(* Logix 5000 project; controller EFlo_iQ_Controller vendor 1 type 14 code 74 rev 20.12; software revision 20.01 *)

TASK MainTask (continuous, watchdog 500 ms) : MainProgram

MODULES
   Local : vendor 1 type 14 code 74 (1768Ctrl5Slot 0, Compact 0, rev 20.12)
      ENET : 1768-ENBT (1768 1, Ethernet 10.10.20.11, rev 3.1)
         EFlo_iQ : ETHERNET-MODULE (Ethernet 192.168.2.16, rev 1.1, Output RPI 10 ms)   // Graco E-Flo iQ Advanced Map
END_MODULES

TYPE ActivePump :
STRUCT
   ControlBits : EFlo_iQ_Control_Bits;
   StatusBits : EFlo_iQ_Status_Bits;
   Information : EFlo_iQ_Pump_Information;
   AdditionalInformation : EFlo_iQ_Pump_Information_ActivePumpOnly;
   DispenseInformation : EFlo_iQ_Dispense_Information;
   StyleInformation : E_Flo_iQ_Style;
   HeartbeatLogic : EFlo_iQ_HeartbeatLogic;
   DataExchange : EFlo_iQ_Pump_Data_Exchange;
END_STRUCT
END_TYPE

TYPE E_Flo_iQ_Style :
STRUCT
   DesiredActiveStyleNumber : INT;
   StyleFieldbusPrechargeRequested : INT;   // XXXX.X bars
   StyleFieldbusFlowrateRequested : INT;   // XXXX cc/min
   StyleFieldbusShotSizeRequested : INT;   // XXXX.XX cc
   StyleFieldbusDValveOnDelayRequested : INT;   // XXXX ms
   StyleFieldbusDValveOffDelayRequested : INT;   // XXXX ms
   StyleFieldbusMotorOnDelayRequested : INT;   // XXXX ms
   StyleFieldbusMotorOffDelayRequested : INT;   // XXXX ms
   ActiveStyleLoaded : INT;
   ActiveStylePrecharge : INT;   // XXXX.X bars
   ActiveStyleFlowrate : INT;   // XXXX cc/min
   ActiveStyleShotSize : INT;   // XXXX.XX cc
   ActiveStyleDispenseValveOnDelay : INT;   // XXXX ms
   ActiveStyleDispenseValveOffDelay : INT;   // XXXX ms
   ActiveStyleMotorOnDelay : INT;   // XXXX ms
   ActiveStyleMotorOffDelay : INT;   // XXXX ms
   ActualStyleFieldbusRequestPrecharge : INT;   // XXXX.X bars
   ActualStyleFieldbusRequestFlowrate : INT;   // XXXX cc/min
   ActualStyleFieldbusRequestShotSize : INT;   // XXXX.XX cc
   ActualStyleFieldbusRequestDValveOnDeley : INT;   // XXXX ms
   ActualStyleFieldbusRequestDValveOffDeley : INT;   // XXXX ms
   ActualStyleFieldbusRequestMotorOnDelay : INT;   // XXXX ms
   ActualStyleFieldbusRequestMotorOffDelay : INT;   // XXXX ms
END_STRUCT
END_TYPE

TYPE EFlo_iQ_Control_Bits :
STRUCT
   SystemEnableRequest : BOOL;
   SystemDisableRequest : BOOL;
   PLCLockoutRequest : BOOL;
   StyleEnableSignal : BOOL;
   StyleGoSignal : BOOL;
   StyleDispenseCompleted : BOOL;
   TandemCrossoverRequest : BOOL;
   PrimingRequest : BOOL;
   ValveDepressurizationRequest : BOOL;
   PlatenDepressurizationRequest : BOOL;
   AutoDepressurizationCancelRequest : BOOL;
   AcknowledgeClearErrorsRequest : BOOL;
END_STRUCT
END_TYPE

TYPE EFlo_iQ_Dispense_Information :
STRUCT
   ActualAmountDispense : DINT;   // XXXX.XX cc
   ActualShotSizeRequested : DINT;   // XXXX.XX cc
END_STRUCT
END_TYPE

TYPE EFlo_iQ_HeartbeatLogic :
STRUCT
   HeartbeatFailure : BOOL;
   EFlo_iQ_Disconnected : BOOL;
   Heartbeat_HighMonitor : COUNTER;
   Heartbeat_LowMonitor : COUNTER;
   Heartbeat_MonitorTimer : TIMER;
   Heartbeat_StopMonitorTimer : BOOL;
END_STRUCT
END_TYPE

TYPE EFlo_iQ_Pump_Data_Exchange :
STRUCT
   PumpDataExchangeActiveCommand : INT;
   PumpDataExchangeActiveValue : DINT;
END_STRUCT
END_TYPE

TYPE EFlo_iQ_Pump_Information :
STRUCT
   ActualPumpFlowrate : INT;   // XXXX cc/min
   OutletPumpPressure : INT;   // XXXX.X bars
END_STRUCT
END_TYPE

TYPE EFlo_iQ_Pump_Information_ActivePumpOnly :
STRUCT
   ValvePressure : INT;   // XXXX.X bars
   PumpPosition : INT;   // X.XXXX inches
   PrimeFlowrateTarget : INT;   // XXXX cc/min
   PrimePressureTarget : INT;   // XXXX.X bars
END_STRUCT
END_TYPE

TYPE EFlo_iQ_Status_Bits :
STRUCT
   Heartbeat : BOOL;
   AutomationReady : BOOL;
   PLCControlActive : BOOL;
   SystemActive : BOOL;
   NoAlarmsPresent : BOOL;
   NoDeviationsPresent : BOOL;
   NoAdvisoriesPresent : BOOL;
   SystemReadyToDispense : BOOL;
   PrechargeDechargeActive : BOOL;
   DispenseInProcess : BOOL;
   DrumIsLow : BOOL;
   DrumIsEmpty : BOOL;
   PumpNotPrimed : BOOL;
   PumpInJobCycle : BOOL;
   PrimingActive : BOOL;
   ValveDepressurizationActive : BOOL;
   PlatenDepressurizationActive : BOOL;
   AutoDepressurizationActive : BOOL;
   AutoDepressurizationHappened : BOOL;
   PumpIsTryingToMove : BOOL;
   PumpIsActuallyMoving : BOOL;
   DispenseValveOpened : BOOL;
   PlatenValveOpened : BOOL;
   TandemActivePump : BOOL;   // 0 = Pump 1 1 = Pump 2
   iQModeActive : BOOL;
   ChangeoverHappenedDuringDispense : BOOL;
END_STRUCT
END_TYPE

TYPE EFlo_iQ_System_Data_Exchange :
STRUCT
   DesiredDataExchangeCommand : INT;
END_STRUCT
END_TYPE

TYPE InactivePump :
STRUCT
   StatusBits : EFlo_iQ_Status_Bits;
   Information : EFlo_iQ_Pump_Information;
   DataExchangeOutputs : EFlo_iQ_Pump_Data_Exchange;
   HeartbeatLogic : EFlo_iQ_HeartbeatLogic;
END_STRUCT
END_TYPE

VAR_GLOBAL   (* controller tags *)
   ActivePump : ActivePump; {access Read Only}
   InactivePump : InactivePump; {access Read Only}
   PumpsDesiredDataExchange : EFlo_iQ_System_Data_Exchange; {access Read Only}
END_VAR

PROGRAM MainProgram   (* main routine MainRoutine *)

ROUTINE EFlo_iQ_Data_Mapping   (* ladder *)
// Mapping_EFlo_iQ_Data_To_Tags
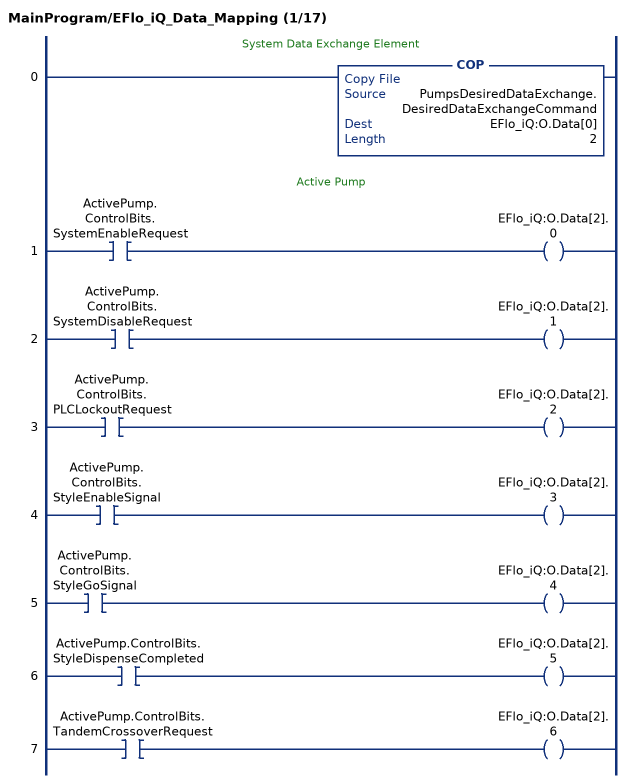
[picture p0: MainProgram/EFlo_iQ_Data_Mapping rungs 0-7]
   // System Data Exchange Element
   0: COP(PumpsDesiredDataExchange.DesiredDataExchangeCommand,EFlo_iQ:O.Data[0],2);
   // Active Pump
   1: XIC(ActivePump.ControlBits.SystemEnableRequest)OTE(EFlo_iQ:O.Data[2].0);
   2: XIC(ActivePump.ControlBits.SystemDisableRequest)OTE(EFlo_iQ:O.Data[2].1);
   3: XIC(ActivePump.ControlBits.PLCLockoutRequest)OTE(EFlo_iQ:O.Data[2].2);
   4: XIC(ActivePump.ControlBits.StyleEnableSignal)OTE(EFlo_iQ:O.Data[2].3);
   5: XIC(ActivePump.ControlBits.StyleGoSignal)OTE(EFlo_iQ:O.Data[2].4);
   6: XIC(ActivePump.ControlBits.StyleDispenseCompleted)OTE(EFlo_iQ:O.Data[2].5);
   7: XIC(ActivePump.ControlBits.TandemCrossoverRequest)OTE(EFlo_iQ:O.Data[2].6);
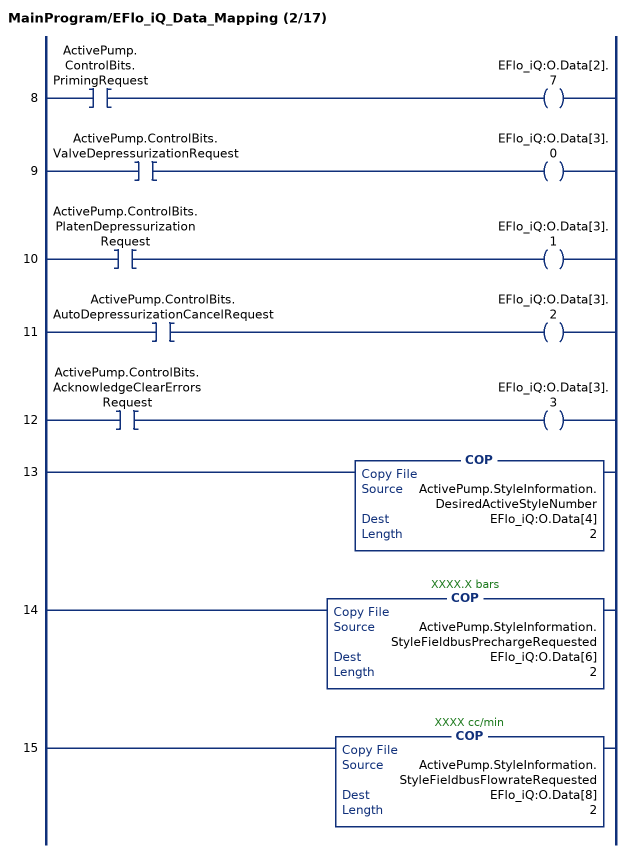
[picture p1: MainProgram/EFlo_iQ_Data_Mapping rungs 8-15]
   8: XIC(ActivePump.ControlBits.PrimingRequest)OTE(EFlo_iQ:O.Data[2].7);
   9: XIC(ActivePump.ControlBits.ValveDepressurizationRequest)OTE(EFlo_iQ:O.Data[3].0);
   10: XIC(ActivePump.ControlBits.PlatenDepressurizationRequest)OTE(EFlo_iQ:O.Data[3].1);
   11: XIC(ActivePump.ControlBits.AutoDepressurizationCancelRequest)OTE(EFlo_iQ:O.Data[3].2);
   12: XIC(ActivePump.ControlBits.AcknowledgeClearErrorsRequest)OTE(EFlo_iQ:O.Data[3].3);
   13: COP(ActivePump.StyleInformation.DesiredActiveStyleNumber,EFlo_iQ:O.Data[4],2);
   14: COP(ActivePump.StyleInformation.StyleFieldbusPrechargeRequested,EFlo_iQ:O.Data[6],2);
   15: COP(ActivePump.StyleInformation.StyleFieldbusFlowrateRequested,EFlo_iQ:O.Data[8],2);
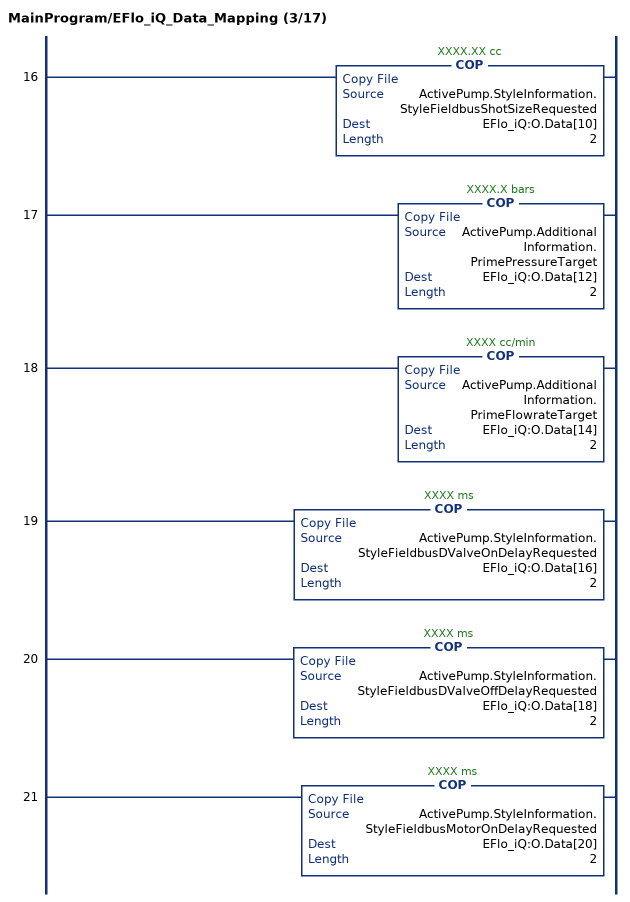
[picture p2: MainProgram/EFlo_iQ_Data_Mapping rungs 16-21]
   16: COP(ActivePump.StyleInformation.StyleFieldbusShotSizeRequested,EFlo_iQ:O.Data[10],2);
   17: COP(ActivePump.AdditionalInformation.PrimePressureTarget,EFlo_iQ:O.Data[12],2);
   18: COP(ActivePump.AdditionalInformation.PrimeFlowrateTarget,EFlo_iQ:O.Data[14],2);
   19: COP(ActivePump.StyleInformation.StyleFieldbusDValveOnDelayRequested,EFlo_iQ:O.Data[16],2);
   20: COP(ActivePump.StyleInformation.StyleFieldbusDValveOffDelayRequested,EFlo_iQ:O.Data[18],2);
   21: COP(ActivePump.StyleInformation.StyleFieldbusMotorOnDelayRequested,EFlo_iQ:O.Data[20],2);
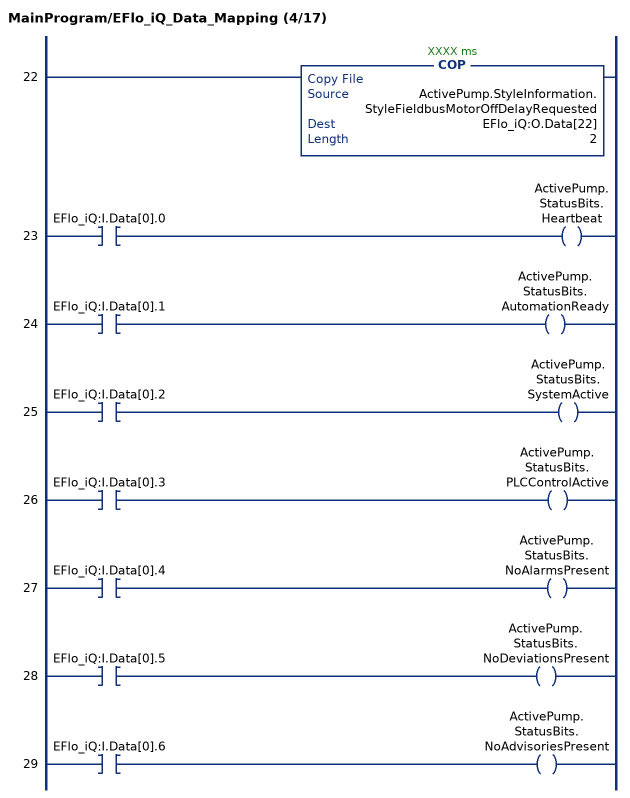
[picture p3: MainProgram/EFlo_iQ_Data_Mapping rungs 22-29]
   22: COP(ActivePump.StyleInformation.StyleFieldbusMotorOffDelayRequested,EFlo_iQ:O.Data[22],2);
   23: XIC(EFlo_iQ:I.Data[0].0)OTE(ActivePump.StatusBits.Heartbeat);
   24: XIC(EFlo_iQ:I.Data[0].1)OTE(ActivePump.StatusBits.AutomationReady);
   25: XIC(EFlo_iQ:I.Data[0].2)OTE(ActivePump.StatusBits.SystemActive);
   26: XIC(EFlo_iQ:I.Data[0].3)OTE(ActivePump.StatusBits.PLCControlActive);
   27: XIC(EFlo_iQ:I.Data[0].4)OTE(ActivePump.StatusBits.NoAlarmsPresent);
   28: XIC(EFlo_iQ:I.Data[0].5)OTE(ActivePump.StatusBits.NoDeviationsPresent);
   29: XIC(EFlo_iQ:I.Data[0].6)OTE(ActivePump.StatusBits.NoAdvisoriesPresent);
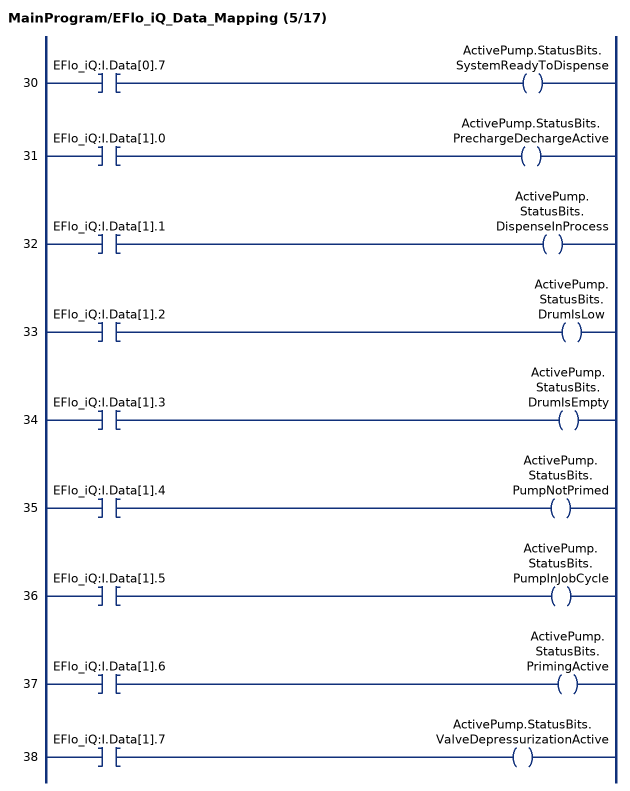
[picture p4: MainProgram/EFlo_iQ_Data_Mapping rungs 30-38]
   30: XIC(EFlo_iQ:I.Data[0].7)OTE(ActivePump.StatusBits.SystemReadyToDispense);
   31: XIC(EFlo_iQ:I.Data[1].0)OTE(ActivePump.StatusBits.PrechargeDechargeActive);
   32: XIC(EFlo_iQ:I.Data[1].1)OTE(ActivePump.StatusBits.DispenseInProcess);
   33: XIC(EFlo_iQ:I.Data[1].2)OTE(ActivePump.StatusBits.DrumIsLow);
   34: XIC(EFlo_iQ:I.Data[1].3)OTE(ActivePump.StatusBits.DrumIsEmpty);
   35: XIC(EFlo_iQ:I.Data[1].4)OTE(ActivePump.StatusBits.PumpNotPrimed);
   36: XIC(EFlo_iQ:I.Data[1].5)OTE(ActivePump.StatusBits.PumpInJobCycle);
   37: XIC(EFlo_iQ:I.Data[1].6)OTE(ActivePump.StatusBits.PrimingActive);
   38: XIC(EFlo_iQ:I.Data[1].7)OTE(ActivePump.StatusBits.ValveDepressurizationActive);
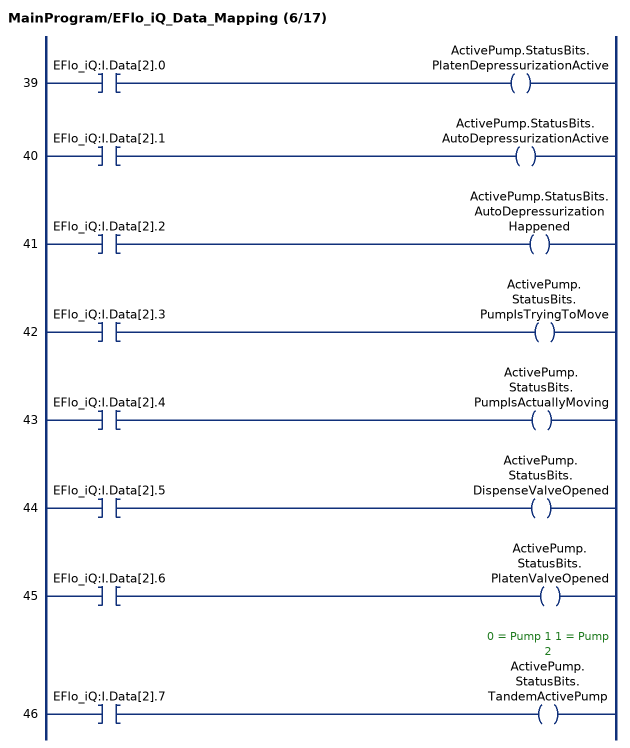
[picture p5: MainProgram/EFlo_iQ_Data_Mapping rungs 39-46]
   39: XIC(EFlo_iQ:I.Data[2].0)OTE(ActivePump.StatusBits.PlatenDepressurizationActive);
   40: XIC(EFlo_iQ:I.Data[2].1)OTE(ActivePump.StatusBits.AutoDepressurizationActive);
   41: XIC(EFlo_iQ:I.Data[2].2)OTE(ActivePump.StatusBits.AutoDepressurizationHappened);
   42: XIC(EFlo_iQ:I.Data[2].3)OTE(ActivePump.StatusBits.PumpIsTryingToMove);
   43: XIC(EFlo_iQ:I.Data[2].4)OTE(ActivePump.StatusBits.PumpIsActuallyMoving);
   44: XIC(EFlo_iQ:I.Data[2].5)OTE(ActivePump.StatusBits.DispenseValveOpened);
   45: XIC(EFlo_iQ:I.Data[2].6)OTE(ActivePump.StatusBits.PlatenValveOpened);
   46: XIC(EFlo_iQ:I.Data[2].7)OTE(ActivePump.StatusBits.TandemActivePump);
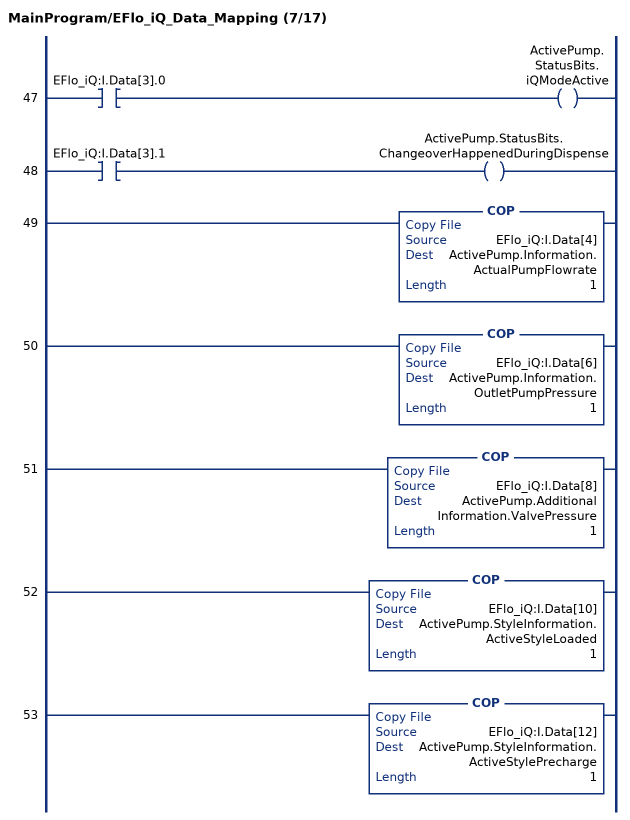
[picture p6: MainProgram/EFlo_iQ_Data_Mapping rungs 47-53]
   47: XIC(EFlo_iQ:I.Data[3].0)OTE(ActivePump.StatusBits.iQModeActive);
   48: XIC(EFlo_iQ:I.Data[3].1)OTE(ActivePump.StatusBits.ChangeoverHappenedDuringDispense);
   49: COP(EFlo_iQ:I.Data[4],ActivePump.Information.ActualPumpFlowrate,1);
   50: COP(EFlo_iQ:I.Data[6],ActivePump.Information.OutletPumpPressure,1);
   51: COP(EFlo_iQ:I.Data[8],ActivePump.AdditionalInformation.ValvePressure,1);
   52: COP(EFlo_iQ:I.Data[10],ActivePump.StyleInformation.ActiveStyleLoaded,1);
   53: COP(EFlo_iQ:I.Data[12],ActivePump.StyleInformation.ActiveStylePrecharge,1);
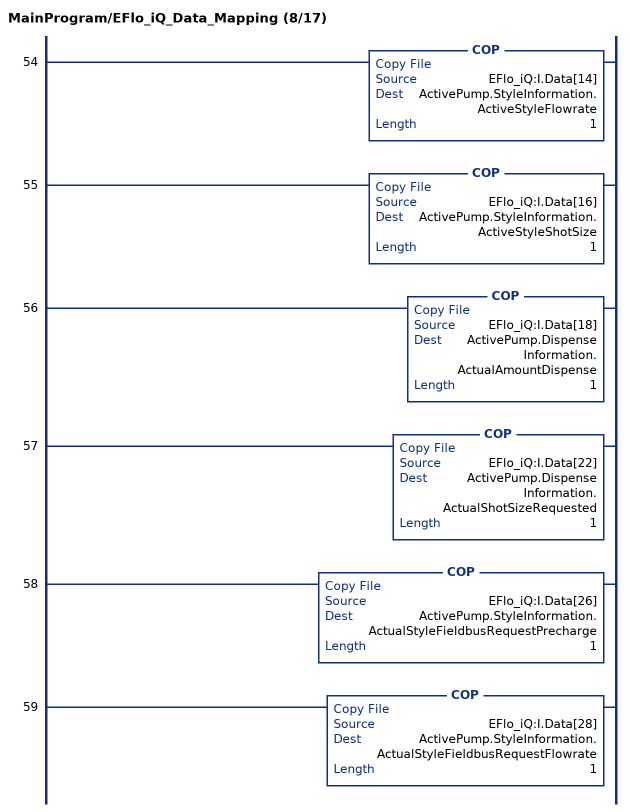
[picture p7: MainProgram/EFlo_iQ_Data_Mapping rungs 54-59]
   54: COP(EFlo_iQ:I.Data[14],ActivePump.StyleInformation.ActiveStyleFlowrate,1);
   55: COP(EFlo_iQ:I.Data[16],ActivePump.StyleInformation.ActiveStyleShotSize,1);
   56: COP(EFlo_iQ:I.Data[18],ActivePump.DispenseInformation.ActualAmountDispense,1);
   57: COP(EFlo_iQ:I.Data[22],ActivePump.DispenseInformation.ActualShotSizeRequested,1);
   58: COP(EFlo_iQ:I.Data[26],ActivePump.StyleInformation.ActualStyleFieldbusRequestPrecharge,1);
   59: COP(EFlo_iQ:I.Data[28],ActivePump.StyleInformation.ActualStyleFieldbusRequestFlowrate,1);
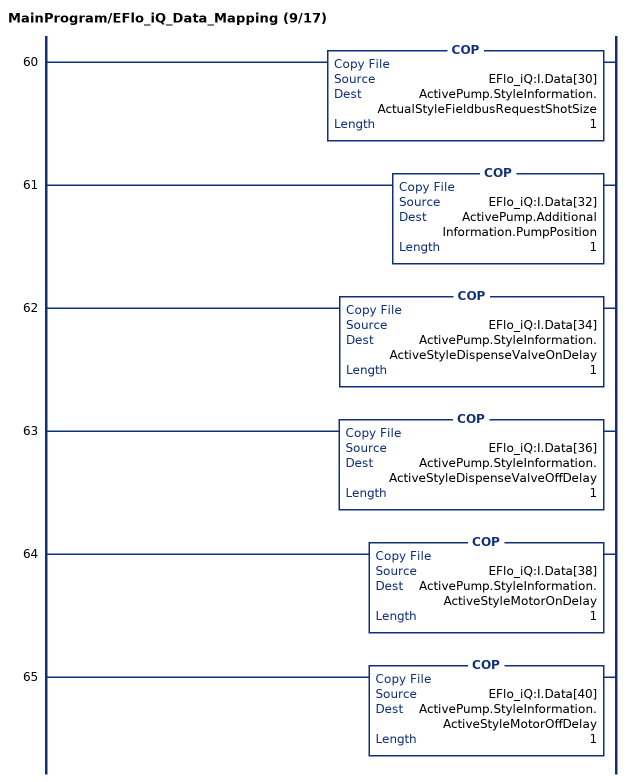
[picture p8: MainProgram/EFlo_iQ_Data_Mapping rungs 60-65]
   60: COP(EFlo_iQ:I.Data[30],ActivePump.StyleInformation.ActualStyleFieldbusRequestShotSize,1);
   61: COP(EFlo_iQ:I.Data[32],ActivePump.AdditionalInformation.PumpPosition,1);
   62: COP(EFlo_iQ:I.Data[34],ActivePump.StyleInformation.ActiveStyleDispenseValveOnDelay,1);
   63: COP(EFlo_iQ:I.Data[36],ActivePump.StyleInformation.ActiveStyleDispenseValveOffDelay,1);
   64: COP(EFlo_iQ:I.Data[38],ActivePump.StyleInformation.ActiveStyleMotorOnDelay,1);
   65: COP(EFlo_iQ:I.Data[40],ActivePump.StyleInformation.ActiveStyleMotorOffDelay,1);
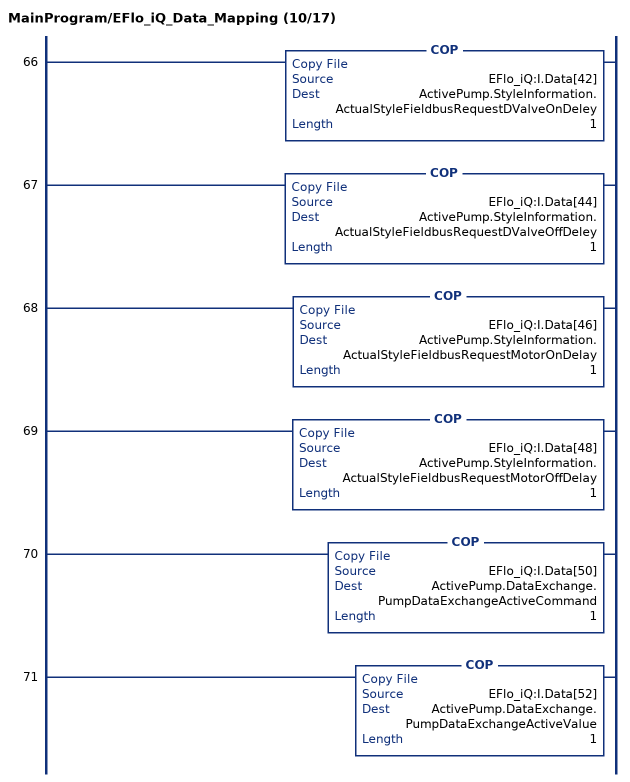
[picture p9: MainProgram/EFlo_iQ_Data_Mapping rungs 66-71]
   66: COP(EFlo_iQ:I.Data[42],ActivePump.StyleInformation.ActualStyleFieldbusRequestDValveOnDeley,1);
   67: COP(EFlo_iQ:I.Data[44],ActivePump.StyleInformation.ActualStyleFieldbusRequestDValveOffDeley,1);
   68: COP(EFlo_iQ:I.Data[46],ActivePump.StyleInformation.ActualStyleFieldbusRequestMotorOnDelay,1);
   69: COP(EFlo_iQ:I.Data[48],ActivePump.StyleInformation.ActualStyleFieldbusRequestMotorOffDelay,1);
   70: COP(EFlo_iQ:I.Data[50],ActivePump.DataExchange.PumpDataExchangeActiveCommand,1);
   71: COP(EFlo_iQ:I.Data[52],ActivePump.DataExchange.PumpDataExchangeActiveValue,1);
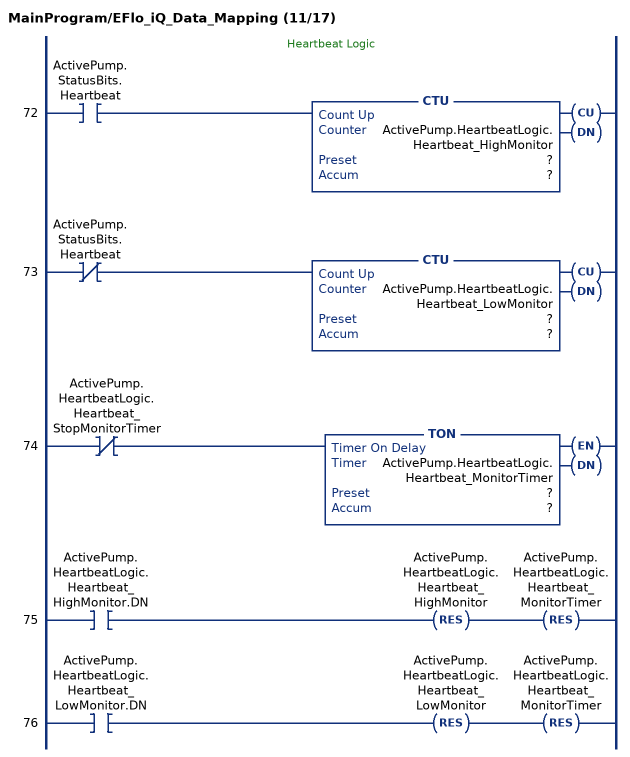
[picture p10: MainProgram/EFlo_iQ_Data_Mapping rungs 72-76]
   // Heartbeat Logic
   72: XIC(ActivePump.StatusBits.Heartbeat)CTU(ActivePump.HeartbeatLogic.Heartbeat_HighMonitor,?,?);
   73: XIO(ActivePump.StatusBits.Heartbeat)CTU(ActivePump.HeartbeatLogic.Heartbeat_LowMonitor,?,?);
   74: XIO(ActivePump.HeartbeatLogic.Heartbeat_StopMonitorTimer)TON(ActivePump.HeartbeatLogic.Heartbeat_MonitorTimer,?,?);
   75: XIC(ActivePump.HeartbeatLogic.Heartbeat_HighMonitor.DN)RES(ActivePump.HeartbeatLogic.Heartbeat_HighMonitor)RES(ActivePump.HeartbeatLogic.Heartbeat_MonitorTimer);
   76: XIC(ActivePump.HeartbeatLogic.Heartbeat_LowMonitor.DN)RES(ActivePump.HeartbeatLogic.Heartbeat_LowMonitor)RES(ActivePump.HeartbeatLogic.Heartbeat_MonitorTimer);
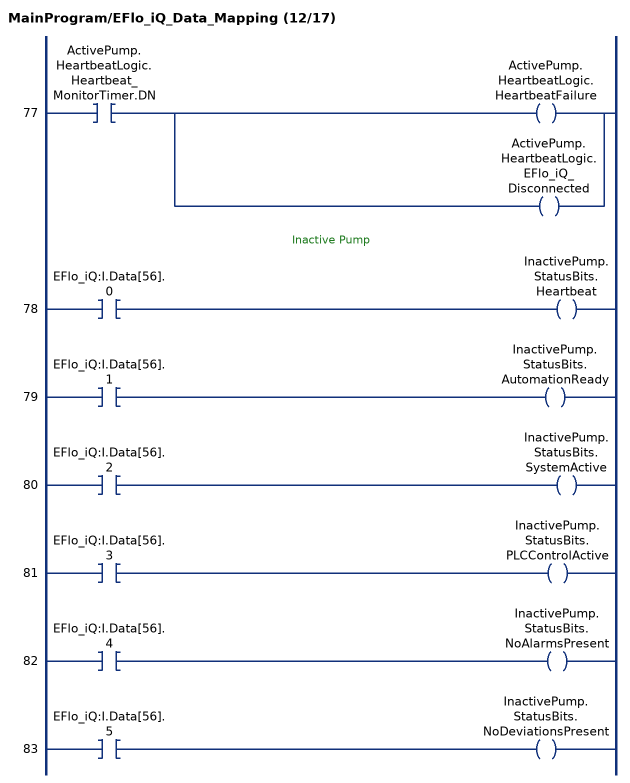
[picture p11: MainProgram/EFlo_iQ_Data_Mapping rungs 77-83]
   77: XIC(ActivePump.HeartbeatLogic.Heartbeat_MonitorTimer.DN)[OTE(ActivePump.HeartbeatLogic.HeartbeatFailure) ,OTE(ActivePump.HeartbeatLogic.EFlo_iQ_Disconnected) ];
   // Inactive Pump
   78: XIC(EFlo_iQ:I.Data[56].0)OTE(InactivePump.StatusBits.Heartbeat);
   79: XIC(EFlo_iQ:I.Data[56].1)OTE(InactivePump.StatusBits.AutomationReady);
   80: XIC(EFlo_iQ:I.Data[56].2)OTE(InactivePump.StatusBits.SystemActive);
   81: XIC(EFlo_iQ:I.Data[56].3)OTE(InactivePump.StatusBits.PLCControlActive);
   82: XIC(EFlo_iQ:I.Data[56].4)OTE(InactivePump.StatusBits.NoAlarmsPresent);
   83: XIC(EFlo_iQ:I.Data[56].5)OTE(InactivePump.StatusBits.NoDeviationsPresent);
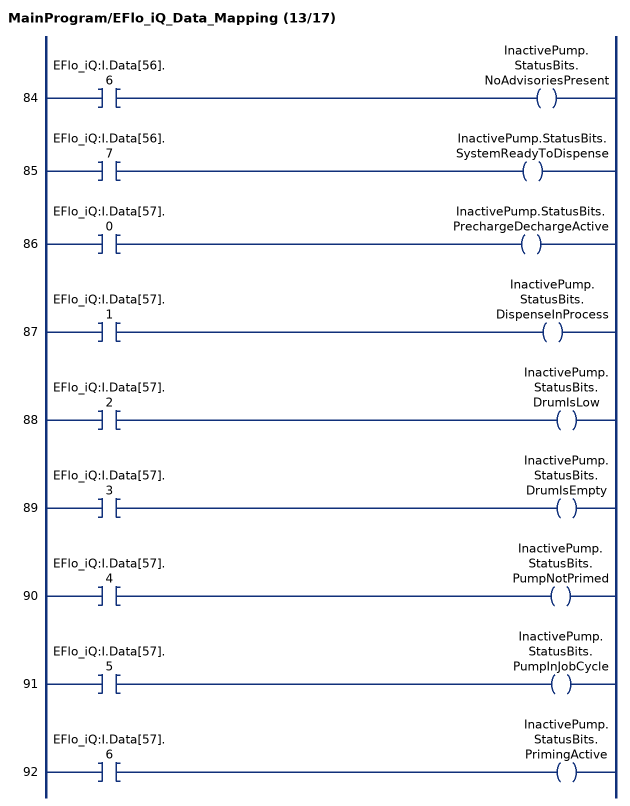
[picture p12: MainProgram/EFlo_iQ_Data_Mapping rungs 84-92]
   84: XIC(EFlo_iQ:I.Data[56].6)OTE(InactivePump.StatusBits.NoAdvisoriesPresent);
   85: XIC(EFlo_iQ:I.Data[56].7)OTE(InactivePump.StatusBits.SystemReadyToDispense);
   86: XIC(EFlo_iQ:I.Data[57].0)OTE(InactivePump.StatusBits.PrechargeDechargeActive);
   87: XIC(EFlo_iQ:I.Data[57].1)OTE(InactivePump.StatusBits.DispenseInProcess);
   88: XIC(EFlo_iQ:I.Data[57].2)OTE(InactivePump.StatusBits.DrumIsLow);
   89: XIC(EFlo_iQ:I.Data[57].3)OTE(InactivePump.StatusBits.DrumIsEmpty);
   90: XIC(EFlo_iQ:I.Data[57].4)OTE(InactivePump.StatusBits.PumpNotPrimed);
   91: XIC(EFlo_iQ:I.Data[57].5)OTE(InactivePump.StatusBits.PumpInJobCycle);
   92: XIC(EFlo_iQ:I.Data[57].6)OTE(InactivePump.StatusBits.PrimingActive);
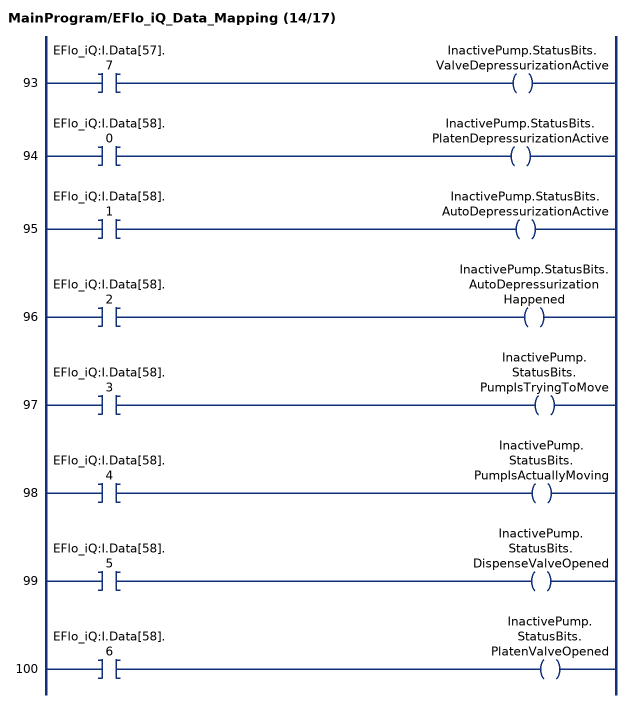
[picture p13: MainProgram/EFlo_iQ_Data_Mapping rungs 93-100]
   93: XIC(EFlo_iQ:I.Data[57].7)OTE(InactivePump.StatusBits.ValveDepressurizationActive);
   94: XIC(EFlo_iQ:I.Data[58].0)OTE(InactivePump.StatusBits.PlatenDepressurizationActive);
   95: XIC(EFlo_iQ:I.Data[58].1)OTE(InactivePump.StatusBits.AutoDepressurizationActive);
   96: XIC(EFlo_iQ:I.Data[58].2)OTE(InactivePump.StatusBits.AutoDepressurizationHappened);
   97: XIC(EFlo_iQ:I.Data[58].3)OTE(InactivePump.StatusBits.PumpIsTryingToMove);
   98: XIC(EFlo_iQ:I.Data[58].4)OTE(InactivePump.StatusBits.PumpIsActuallyMoving);
   99: XIC(EFlo_iQ:I.Data[58].5)OTE(InactivePump.StatusBits.DispenseValveOpened);
   100: XIC(EFlo_iQ:I.Data[58].6)OTE(InactivePump.StatusBits.PlatenValveOpened);
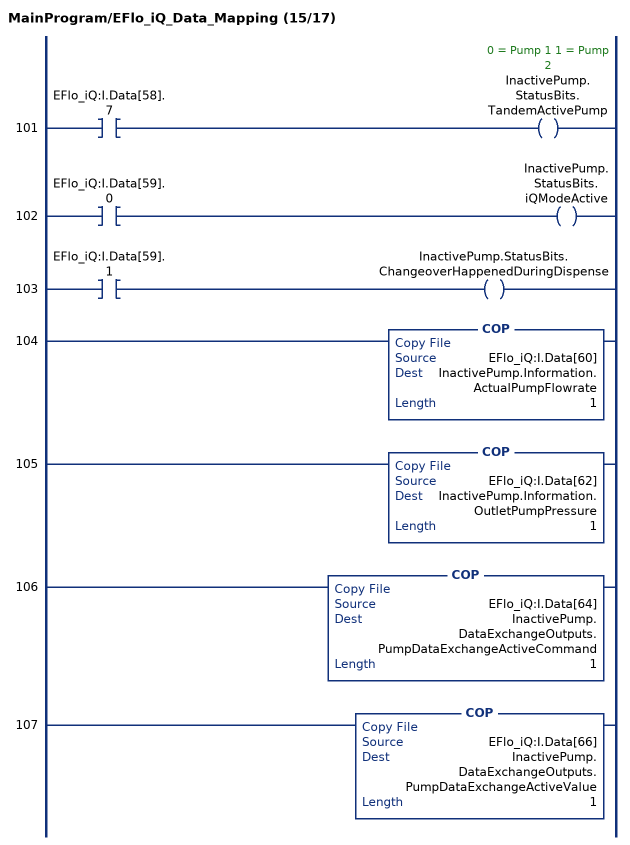
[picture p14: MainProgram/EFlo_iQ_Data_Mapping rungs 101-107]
   101: XIC(EFlo_iQ:I.Data[58].7)OTE(InactivePump.StatusBits.TandemActivePump);
   102: XIC(EFlo_iQ:I.Data[59].0)OTE(InactivePump.StatusBits.iQModeActive);
   103: XIC(EFlo_iQ:I.Data[59].1)OTE(InactivePump.StatusBits.ChangeoverHappenedDuringDispense);
   104: COP(EFlo_iQ:I.Data[60],InactivePump.Information.ActualPumpFlowrate,1);
   105: COP(EFlo_iQ:I.Data[62],InactivePump.Information.OutletPumpPressure,1);
   106: COP(EFlo_iQ:I.Data[64],InactivePump.DataExchangeOutputs.PumpDataExchangeActiveCommand,1);
   107: COP(EFlo_iQ:I.Data[66],InactivePump.DataExchangeOutputs.PumpDataExchangeActiveValue,1);
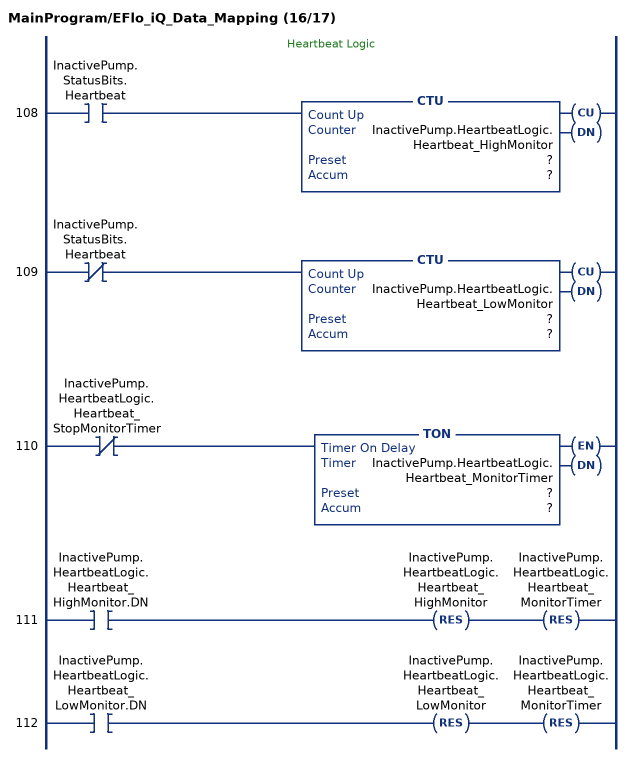
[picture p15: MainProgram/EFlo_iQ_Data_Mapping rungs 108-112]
   // Heartbeat Logic
   108: XIC(InactivePump.StatusBits.Heartbeat)CTU(InactivePump.HeartbeatLogic.Heartbeat_HighMonitor,?,?);
   109: XIO(InactivePump.StatusBits.Heartbeat)CTU(InactivePump.HeartbeatLogic.Heartbeat_LowMonitor,?,?);
   110: XIO(InactivePump.HeartbeatLogic.Heartbeat_StopMonitorTimer)TON(InactivePump.HeartbeatLogic.Heartbeat_MonitorTimer,?,?);
   111: XIC(InactivePump.HeartbeatLogic.Heartbeat_HighMonitor.DN)RES(InactivePump.HeartbeatLogic.Heartbeat_HighMonitor)RES(InactivePump.HeartbeatLogic.Heartbeat_MonitorTimer);
   112: XIC(InactivePump.HeartbeatLogic.Heartbeat_LowMonitor.DN)RES(InactivePump.HeartbeatLogic.Heartbeat_LowMonitor)RES(InactivePump.HeartbeatLogic.Heartbeat_MonitorTimer);
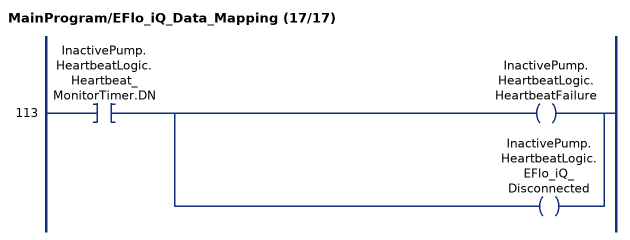
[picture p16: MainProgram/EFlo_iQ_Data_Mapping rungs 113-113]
   113: XIC(InactivePump.HeartbeatLogic.Heartbeat_MonitorTimer.DN)[OTE(InactivePump.HeartbeatLogic.HeartbeatFailure) ,OTE(InactivePump.HeartbeatLogic.EFlo_iQ_Disconnected) ];
END_ROUTINE

ROUTINE MainRoutine   (* ladder *)
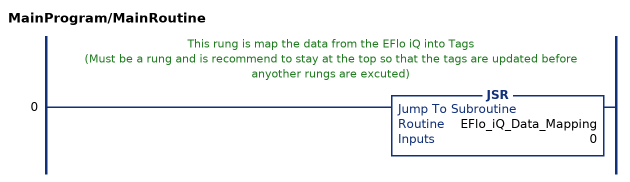
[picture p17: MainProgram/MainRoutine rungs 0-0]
   // This rung is map the data from the EFlo iQ into Tags
   // (Must be a rung and is recommend to stay at the top so that the tags are updated before anyother rungs are excuted)
   0: JSR(EFlo_iQ_Data_Mapping,0);
END_ROUTINE
END_PROGRAM
